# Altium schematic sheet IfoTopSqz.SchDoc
size A; DocumentNumber: 1; SheetNumber: 1; SheetTotal: 10; pInstance: Corner
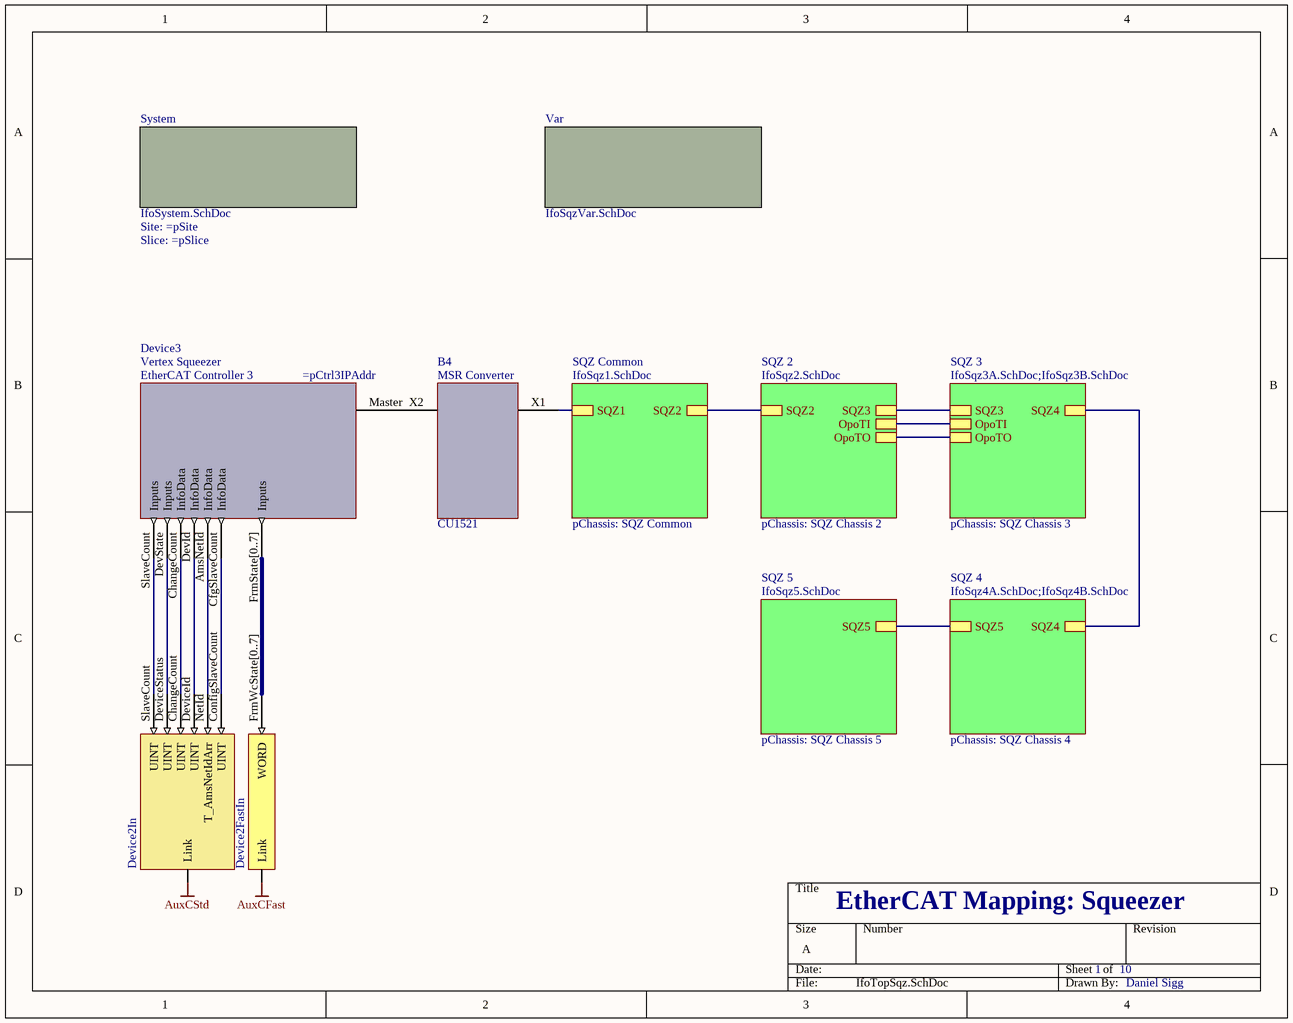
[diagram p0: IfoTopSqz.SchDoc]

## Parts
B4  MSR Converter  Part Number: CU1521  (mechanical)
Device3  Vertex Squeezer  DeviceDesc: EtherCAT Controller 3  (mechanical)
V89  Device2In  (no BOM)
V90  Device2FastIn  (no BOM)

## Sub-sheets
SQZ 2 = IfoSqz2.SchDoc: SQZ2, SQZ3, OpoTI, OpoTO  | pChassis: SQZ Chassis 2
SQZ 3 = IfoSqz3A.SchDoc;IfoSqz3B.SchDoc: SQZ3, OpoTI, OpoTO, SQZ4  | pChassis: SQZ Chassis 3
SQZ 4 = IfoSqz4A.SchDoc;IfoSqz4B.SchDoc: SQZ4, SQZ5  | pChassis: SQZ Chassis 4
SQZ 5 = IfoSqz5.SchDoc: SQZ5  | pChassis: SQZ Chassis 5
SQZ Common = IfoSqz1.SchDoc: SQZ1, SQZ2  | pChassis: SQZ Common
System = IfoSystem.SchDoc: no entries  | Site: =pSite; Slice: =pSlice
Var = IfoSqzVar.SchDoc: no entries

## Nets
AuxCFast: V90.?1(Link)
AuxCStd: V89.?1(Link)
NetB4_X1: B4.X1(B) ; sheet SQZ Common/SQZ1
NetB4_X2: B4.X2(A) Device3.Master(B)
NetDevice3_AmsNetId: Device3.AmsNetId(InfoData) V89.NetId(T_AmsNetIdArr)
NetDevice3_CfgSlaveCount: Device3.CfgSlaveCount(InfoData) V89.ConfigSlaveCount(UINT)
NetDevice3_ChangeCount: Device3.ChangeCount(InfoData) V89.ChangeCount(UINT)
NetDevice3_DevId: Device3.DevId(InfoData) V89.DeviceId(UINT)
NetDevice3_DevState: Device3.DevState(Inputs) V89.DeviceStatus(UINT)
NetDevice3_FrmState[0..7]: Device3.FrmState[0..7](Inputs) V90.FrmWcState[0..7](WORD)
NetDevice3_SlaveCount: Device3.SlaveCount(Inputs) V89.SlaveCount(UINT)
(unnamed): sheet SQZ Common/SQZ2, sheet SQZ 2/SQZ2
(unnamed): sheet SQZ 2/SQZ3, sheet SQZ 3/SQZ3  [a separate net that carries the same name]
(unnamed): sheet SQZ 2/OpoTI, sheet SQZ 3/OpoTI  [a separate net that carries the same name]
(unnamed): sheet SQZ 2/OpoTO, sheet SQZ 3/OpoTO  [a separate net that carries the same name]
(unnamed): sheet SQZ 3/SQZ4, sheet SQZ 4/SQZ4  [a separate net that carries the same name]
(unnamed): sheet SQZ 4/SQZ5, sheet SQZ 5/SQZ5  [a separate net that carries the same name]

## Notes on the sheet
- EtherCAT Mapping: Squeezer
- Daniel Sigg

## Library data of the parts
B4 = MediaConverterCAT5toFiber: EtherCAT Media Converter; BoxType: Box; BoxNextB: STIDPCUW; BoxPrev: OPANLZUF; PortPrevFull: 1000/; Fullname: TIID^Vertex Squeezer (EtherCAT)^MSR Converter (CU1521); BoxAddr: 1001; Disabled: False
Device3 = EtherCATMaster: EtherCAT Master; Part Number: FC9022; DeviceData: 0001053F990B; BoxNextB: BXBUSGVQ; Fullname: TIID^Vertex Squeezer (EtherCAT); BoxSubType: 111; Disabled: False
V89 = PLCInfo_MasterInfoInStruct: MasterInfoInStruct; PLC: H1AuxCorner; Task: AuxCStd; BoxType: Variable; Instance: H1AuxCorner Instance
V90 = PLCInfo_MasterInfoFastInStruct: MasterInfoFastInStruct; PLC: H1AuxCorner; Task: AuxCFast; BoxType: Variable; Instance: H1AuxCorner Instance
